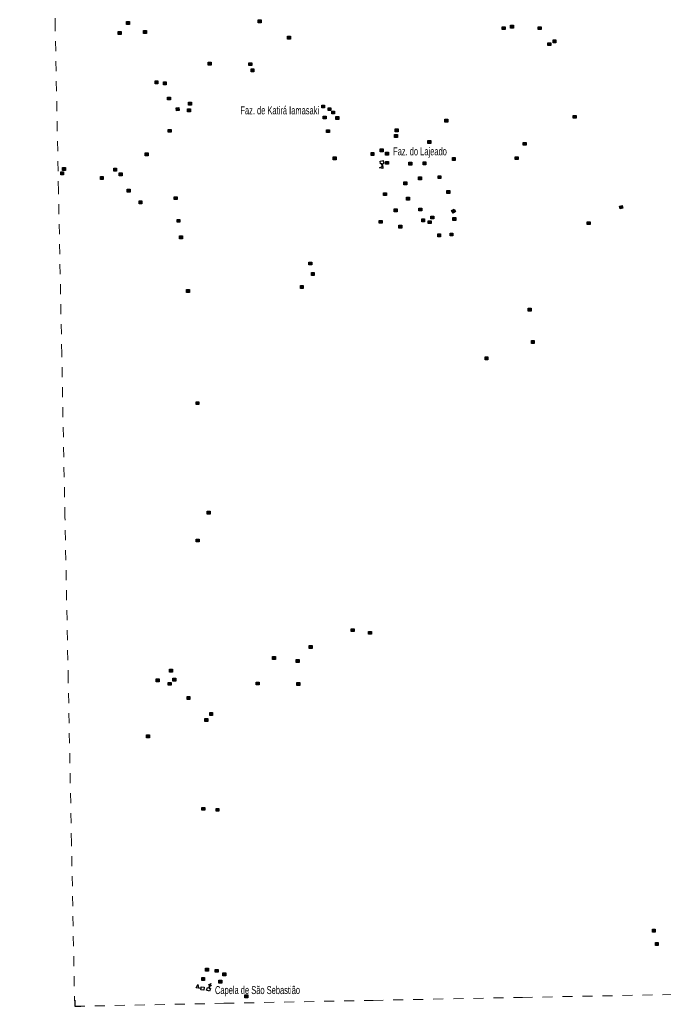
# Model space of a CAD drawing. Extents: x 220.8 to 246.7, y 7287.6 to 7315.8.
# Drawn here: x 220.75 to 227.18, y 7287.6 to 7297.47 of the extents above; entities that cross this region are included whole.
import ezdxf
from ezdxf.enums import TextEntityAlignment as Align

# ---------------------------------------------------------------- set-up
doc = ezdxf.new("R2010")
doc.units = 0
doc.header["$LTSCALE"] = 0.032
doc.linetypes.add('SHORT_DASHED', pattern=[2.7, 1.5, -1.2])
for name, color, linetype, lineweight in [('2', 7, 'Continuous', 25), ('4', 7, 'Continuous', 25), ('58', 7, 'SHORT_DASHED', 13), ('6', 7, 'Continuous', 25), ('63', 7, 'Continuous', 25)]:
    doc.layers.add(name, color=color, linetype=linetype, lineweight=lineweight)
doc.layers.add('61', color=7, linetype='Continuous')

msp = doc.modelspace()

# ---------------------------------------------------------------- hatches: boundary and pattern name
at = {"layer": '2'}
for points in [[(221.821, 7297.4477), (221.85, 7297.4477), (221.85, 7297.4187), (221.821, 7297.4187)], [(223.1357, 7297.4648), (223.1647, 7297.4648), (223.1647, 7297.4358), (223.1357, 7297.4358)], [(221.7374, 7297.348), (221.7664, 7297.348), (221.7664, 7297.319), (221.7374, 7297.319)], [(221.9914, 7297.3577), (222.0204, 7297.3577), (222.0204, 7297.3287), (221.9914, 7297.3287)], [(225.5724, 7297.3963), (225.6014, 7297.3963), (225.6014, 7297.3673), (225.5724, 7297.3673)], [(225.6572, 7297.412), (225.6862, 7297.412), (225.6862, 7297.383), (225.6572, 7297.383)], [(225.9335, 7297.3963), (225.9625, 7297.3963), (225.9625, 7297.3673), (225.9335, 7297.3673)], [(223.4296, 7297.3019), (223.4586, 7297.3019), (223.4586, 7297.2729), (223.4296, 7297.2729)], [(226.0308, 7297.2362), (226.0598, 7297.2362), (226.0598, 7297.2072), (226.0308, 7297.2072)], [(226.081, 7297.2644), (226.11, 7297.2644), (226.11, 7297.2354), (226.081, 7297.2354)], [(222.6359, 7297.0421), (222.6649, 7297.0421), (222.6649, 7297.0131), (222.6359, 7297.0131)], [(223.043, 7297.0363), (223.072, 7297.0363), (223.072, 7297.0073), (223.043, 7297.0073)], [(223.0644, 7296.9759), (223.0934, 7296.9759), (223.0934, 7296.9469), (223.0644, 7296.9469)], [(222.1059, 7296.854), (222.1349, 7296.854), (222.1349, 7296.825), (222.1059, 7296.825)], [(222.1888, 7296.845), (222.2178, 7296.845), (222.2178, 7296.816), (222.1888, 7296.816)], [(222.2303, 7296.6935), (222.2593, 7296.6935), (222.2593, 7296.6645), (222.2303, 7296.6645)], [(222.4412, 7296.6413), (222.4702, 7296.6413), (222.4702, 7296.6123), (222.4412, 7296.6123)], [(222.3155, 7296.5856), (222.3443, 7296.5889), (222.3477, 7296.5601), (222.3188, 7296.5567)], [(222.4304, 7296.5746), (222.4594, 7296.5746), (222.4594, 7296.5456), (222.4304, 7296.5456)], [(223.771, 7296.6131), (223.8, 7296.6131), (223.8, 7296.5841), (223.771, 7296.5841)], [(223.8339, 7296.5869), (223.8629, 7296.5869), (223.8629, 7296.5579), (223.8339, 7296.5579)], [(223.8706, 7296.5528), (223.8996, 7296.5528), (223.8996, 7296.5238), (223.8706, 7296.5238)], [(223.7867, 7296.5031), (223.8157, 7296.5031), (223.8157, 7296.4741), (223.7867, 7296.4741)], [(223.9125, 7296.4978), (223.9415, 7296.4978), (223.9415, 7296.4688), (223.9125, 7296.4688)], [(225.0007, 7296.4709), (225.0297, 7296.4709), (225.0297, 7296.4419), (225.0007, 7296.4419)], [(226.2829, 7296.5099), (226.3119, 7296.5099), (226.3119, 7296.4809), (226.2829, 7296.4809)], [(222.2371, 7296.3698), (222.2661, 7296.3698), (222.2661, 7296.3408), (222.2371, 7296.3408)], [(223.8182, 7296.3668), (223.8472, 7296.3668), (223.8472, 7296.3378), (223.8182, 7296.3378)], [(224.5043, 7296.3746), (224.5333, 7296.3746), (224.5333, 7296.3456), (224.5043, 7296.3456)], [(224.4984, 7296.318), (224.5274, 7296.318), (224.5274, 7296.289), (224.4984, 7296.289)], [(224.8313, 7296.259), (224.8603, 7296.259), (224.8603, 7296.23), (224.8313, 7296.23)], [(224.3555, 7296.1751), (224.3845, 7296.1751), (224.3845, 7296.1461), (224.3555, 7296.1461)], [(224.4091, 7296.1424), (224.4381, 7296.1424), (224.4381, 7296.1134), (224.4091, 7296.1134)], [(225.7831, 7296.2396), (225.8121, 7296.2396), (225.8121, 7296.2106), (225.7831, 7296.2106)], [(222.0066, 7296.1357), (222.0356, 7296.1357), (222.0356, 7296.1067), (222.0066, 7296.1067)], [(223.8851, 7296.0947), (223.9141, 7296.0947), (223.9141, 7296.0657), (223.8851, 7296.0657)], [(224.2632, 7296.1394), (224.2922, 7296.1394), (224.2922, 7296.1104), (224.2632, 7296.1104)], [(224.4091, 7296.0501), (224.4381, 7296.0501), (224.4381, 7296.0211), (224.4091, 7296.0211)], [(224.7827, 7296.0441), (224.8117, 7296.0441), (224.8117, 7296.0151), (224.7827, 7296.0151)], [(225.0756, 7296.0884), (225.1046, 7296.0884), (225.1046, 7296.0594), (225.0756, 7296.0594)], [(225.7036, 7296.0964), (225.7326, 7296.0964), (225.7326, 7296.0674), (225.7036, 7296.0674)], [(221.1639, 7295.9448), (221.1929, 7295.9448), (221.1929, 7295.9158), (221.1639, 7295.9158)], [(221.1819, 7295.988), (221.2109, 7295.988), (221.2109, 7295.959), (221.1819, 7295.959)], [(221.6933, 7295.9808), (221.7223, 7295.9808), (221.7223, 7295.9518), (221.6933, 7295.9518)], [(224.6413, 7296.0411), (224.6703, 7296.0411), (224.6703, 7296.0121), (224.6413, 7296.0121)], [(221.5601, 7295.898), (221.5891, 7295.898), (221.5891, 7295.869), (221.5601, 7295.869)], [(221.7473, 7295.934), (221.7763, 7295.934), (221.7763, 7295.905), (221.7473, 7295.905)], [(224.7384, 7295.8943), (224.7674, 7295.8943), (224.7674, 7295.8653), (224.7384, 7295.8653)], [(224.9323, 7295.9066), (224.9613, 7295.9066), (224.9613, 7295.8776), (224.9323, 7295.8776)], [(221.8288, 7295.7718), (221.8578, 7295.7718), (221.8578, 7295.7428), (221.8288, 7295.7428)], [(224.5906, 7295.8451), (224.6196, 7295.8451), (224.6196, 7295.8161), (224.5906, 7295.8161)], [(225.0216, 7295.7589), (225.0506, 7295.7589), (225.0506, 7295.7299), (225.0216, 7295.7299)], [(221.9459, 7295.6547), (221.9749, 7295.6547), (221.9749, 7295.6257), (221.9459, 7295.6257)], [(222.2973, 7295.6965), (222.3263, 7295.6965), (222.3263, 7295.6675), (222.2973, 7295.6675)], [(224.3875, 7295.7373), (224.4165, 7295.7373), (224.4165, 7295.7083), (224.3875, 7295.7083)], [(224.6184, 7295.6911), (224.6474, 7295.6911), (224.6474, 7295.6621), (224.6184, 7295.6621)], [(224.4952, 7295.5742), (224.5242, 7295.5742), (224.5242, 7295.5452), (224.4952, 7295.5452)], [(224.7415, 7295.5834), (224.7705, 7295.5834), (224.7705, 7295.5544), (224.7415, 7295.5544)], [(225.0685, 7295.5575), (225.0931, 7295.5728), (225.1085, 7295.5482), (225.0839, 7295.5329)], [(226.7446, 7295.6033), (226.7727, 7295.6106), (226.78, 7295.5825), (226.752, 7295.5752)], [(222.3252, 7295.4706), (222.3542, 7295.4706), (222.3542, 7295.4416), (222.3252, 7295.4416)], [(224.3444, 7295.4603), (224.3734, 7295.4603), (224.3734, 7295.4313), (224.3444, 7295.4313)], [(224.7692, 7295.4757), (224.7982, 7295.4757), (224.7982, 7295.4467), (224.7692, 7295.4467)], [(224.8338, 7295.4572), (224.8628, 7295.4572), (224.8628, 7295.4282), (224.8338, 7295.4282)], [(224.8615, 7295.5034), (224.8905, 7295.5034), (224.8905, 7295.4744), (224.8615, 7295.4744)], [(225.0801, 7295.488), (225.1091, 7295.488), (225.1091, 7295.459), (225.0801, 7295.459)], [(224.5414, 7295.411), (224.5704, 7295.411), (224.5704, 7295.382), (224.5414, 7295.382)], [(226.4225, 7295.4471), (226.4515, 7295.4471), (226.4515, 7295.4181), (226.4225, 7295.4181)], [(222.3503, 7295.306), (222.3793, 7295.306), (222.3793, 7295.277), (222.3503, 7295.277)], [(224.9293, 7295.3248), (224.9583, 7295.3248), (224.9583, 7295.2958), (224.9293, 7295.2958)], [(225.0524, 7295.3341), (225.0814, 7295.3341), (225.0814, 7295.3051), (225.0524, 7295.3051)], [(223.6429, 7295.0432), (223.6719, 7295.0432), (223.6719, 7295.0142), (223.6429, 7295.0142)], [(223.6678, 7294.9381), (223.6968, 7294.9381), (223.6968, 7294.9091), (223.6678, 7294.9091)], [(222.4202, 7294.7687), (222.4492, 7294.7687), (222.4492, 7294.7397), (222.4202, 7294.7397)], [(223.5574, 7294.8085), (223.5864, 7294.8085), (223.5864, 7294.7795), (223.5574, 7294.7795)], [(225.8327, 7294.581), (225.8617, 7294.581), (225.8617, 7294.552), (225.8327, 7294.552)], [(225.865, 7294.2581), (225.894, 7294.2581), (225.894, 7294.2291), (225.865, 7294.2291)], [(225.4022, 7294.0967), (225.4312, 7294.0967), (225.4312, 7294.0677), (225.4022, 7294.0677)], [(222.5156, 7293.6474), (222.5446, 7293.6474), (222.5446, 7293.6184), (222.5156, 7293.6184)], [(222.6278, 7292.5537), (222.6568, 7292.5537), (222.6568, 7292.5247), (222.6278, 7292.5247)], [(222.5162, 7292.2747), (222.5452, 7292.2747), (222.5452, 7292.2457), (222.5162, 7292.2457)], [(224.0653, 7291.378), (224.0943, 7291.378), (224.0943, 7291.349), (224.0653, 7291.349)], [(224.2372, 7291.3515), (224.2662, 7291.3515), (224.2662, 7291.3225), (224.2372, 7291.3225)], [(223.6455, 7291.2094), (223.6745, 7291.2094), (223.6745, 7291.1804), (223.6455, 7291.1804)], [(223.2785, 7291.1003), (223.3075, 7291.1003), (223.3075, 7291.0713), (223.2785, 7291.0713)], [(223.5165, 7291.0705), (223.5455, 7291.0705), (223.5455, 7291.0415), (223.5165, 7291.0415)], [(222.25, 7290.9735), (222.279, 7290.9735), (222.279, 7290.9445), (222.25, 7290.9445)], [(222.1182, 7290.8755), (222.1472, 7290.8755), (222.1472, 7290.8465), (222.1182, 7290.8465)], [(222.2365, 7290.8417), (222.2655, 7290.8417), (222.2655, 7290.8127), (222.2365, 7290.8127)], [(222.2838, 7290.8823), (222.3128, 7290.8823), (222.3128, 7290.8533), (222.2838, 7290.8533)], [(223.1166, 7290.8451), (223.1456, 7290.8451), (223.1456, 7290.8161), (223.1166, 7290.8161)], [(223.5231, 7290.8391), (223.5521, 7290.8391), (223.5521, 7290.8101), (223.5231, 7290.8101)], [(222.4257, 7290.6998), (222.4547, 7290.6998), (222.4547, 7290.6708), (222.4257, 7290.6708)], [(222.652, 7290.541), (222.681, 7290.541), (222.681, 7290.512), (222.652, 7290.512)], [(222.6047, 7290.4802), (222.6337, 7290.4802), (222.6337, 7290.4512), (222.6047, 7290.4512)], [(222.0207, 7290.3172), (222.0497, 7290.3172), (222.0497, 7290.2882), (222.0207, 7290.2882)], [(222.5736, 7289.5915), (222.6026, 7289.5915), (222.6026, 7289.5625), (222.5736, 7289.5625)], [(222.715, 7289.5816), (222.744, 7289.5816), (222.744, 7289.5526), (222.715, 7289.5526)], [(227.0736, 7288.3731), (227.1026, 7288.3731), (227.1026, 7288.3441), (227.0736, 7288.3441)], [(227.1033, 7288.2411), (227.1323, 7288.2411), (227.1323, 7288.2121), (227.1033, 7288.2121)], [(222.6094, 7287.9844), (222.6384, 7287.9844), (222.6384, 7287.9554), (222.6094, 7287.9554)], [(222.7071, 7287.9719), (222.7361, 7287.9719), (222.7361, 7287.9429), (222.7071, 7287.9429)], [(222.5719, 7287.8908), (222.6009, 7287.8908), (222.6009, 7287.8618), (222.5719, 7287.8618)], [(222.7424, 7287.8638), (222.7714, 7287.8638), (222.7714, 7287.8348), (222.7424, 7287.8348)], [(222.784, 7287.9366), (222.813, 7287.9366), (222.813, 7287.9076), (222.784, 7287.9076)], [(223.0022, 7287.7162), (223.0312, 7287.7162), (223.0312, 7287.6872), (223.0022, 7287.6872)]]:
    msp.add_hatch(color=256, dxfattribs=at).paths.add_polyline_path(points)

# ---------------------------------------------------------------- linework, layer by layer
for points in [[(221.821, 7297.4477), (221.85, 7297.4477), (221.85, 7297.4187), (221.821, 7297.4187)], [(223.1357, 7297.4648), (223.1647, 7297.4648), (223.1647, 7297.4358), (223.1357, 7297.4358)], [(221.7374, 7297.348), (221.7664, 7297.348), (221.7664, 7297.319), (221.7374, 7297.319)], [(221.9914, 7297.3577), (222.0204, 7297.3577), (222.0204, 7297.3287), (221.9914, 7297.3287)], [(225.5724, 7297.3963), (225.6014, 7297.3963), (225.6014, 7297.3673), (225.5724, 7297.3673)], [(225.6572, 7297.412), (225.6862, 7297.412), (225.6862, 7297.383), (225.6572, 7297.383)], [(225.9335, 7297.3963), (225.9625, 7297.3963), (225.9625, 7297.3673), (225.9335, 7297.3673)], [(223.4296, 7297.3019), (223.4586, 7297.3019), (223.4586, 7297.2729), (223.4296, 7297.2729)], [(226.0308, 7297.2362), (226.0598, 7297.2362), (226.0598, 7297.2072), (226.0308, 7297.2072)], [(226.081, 7297.2644), (226.11, 7297.2644), (226.11, 7297.2354), (226.081, 7297.2354)], [(222.6359, 7297.0421), (222.6649, 7297.0421), (222.6649, 7297.0131), (222.6359, 7297.0131)], [(223.043, 7297.0363), (223.072, 7297.0363), (223.072, 7297.0073), (223.043, 7297.0073)], [(223.0644, 7296.9759), (223.0934, 7296.9759), (223.0934, 7296.9469), (223.0644, 7296.9469)], [(222.1059, 7296.854), (222.1349, 7296.854), (222.1349, 7296.825), (222.1059, 7296.825)], [(222.1888, 7296.845), (222.2178, 7296.845), (222.2178, 7296.816), (222.1888, 7296.816)], [(222.2303, 7296.6935), (222.2593, 7296.6935), (222.2593, 7296.6645), (222.2303, 7296.6645)], [(222.4412, 7296.6413), (222.4702, 7296.6413), (222.4702, 7296.6123), (222.4412, 7296.6123)], [(222.3155, 7296.5856), (222.3443, 7296.5889), (222.3477, 7296.5601), (222.3188, 7296.5567)], [(222.4304, 7296.5746), (222.4594, 7296.5746), (222.4594, 7296.5456), (222.4304, 7296.5456)], [(223.771, 7296.6131), (223.8, 7296.6131), (223.8, 7296.5841), (223.771, 7296.5841)], [(223.8339, 7296.5869), (223.8629, 7296.5869), (223.8629, 7296.5579), (223.8339, 7296.5579)], [(223.8706, 7296.5528), (223.8996, 7296.5528), (223.8996, 7296.5238), (223.8706, 7296.5238)], [(223.7867, 7296.5031), (223.8157, 7296.5031), (223.8157, 7296.4741), (223.7867, 7296.4741)], [(223.9125, 7296.4978), (223.9415, 7296.4978), (223.9415, 7296.4688), (223.9125, 7296.4688)], [(225.0007, 7296.4709), (225.0297, 7296.4709), (225.0297, 7296.4419), (225.0007, 7296.4419)], [(226.2829, 7296.5099), (226.3119, 7296.5099), (226.3119, 7296.4809), (226.2829, 7296.4809)], [(222.2371, 7296.3698), (222.2661, 7296.3698), (222.2661, 7296.3408), (222.2371, 7296.3408)], [(223.8182, 7296.3668), (223.8472, 7296.3668), (223.8472, 7296.3378), (223.8182, 7296.3378)], [(224.5043, 7296.3746), (224.5333, 7296.3746), (224.5333, 7296.3456), (224.5043, 7296.3456)], [(224.4984, 7296.318), (224.5274, 7296.318), (224.5274, 7296.289), (224.4984, 7296.289)], [(224.8313, 7296.259), (224.8603, 7296.259), (224.8603, 7296.23), (224.8313, 7296.23)], [(224.3555, 7296.1751), (224.3845, 7296.1751), (224.3845, 7296.1461), (224.3555, 7296.1461)], [(224.4091, 7296.1424), (224.4381, 7296.1424), (224.4381, 7296.1134), (224.4091, 7296.1134)], [(225.7831, 7296.2396), (225.8121, 7296.2396), (225.8121, 7296.2106), (225.7831, 7296.2106)], [(222.0066, 7296.1357), (222.0356, 7296.1357), (222.0356, 7296.1067), (222.0066, 7296.1067)], [(223.8851, 7296.0947), (223.9141, 7296.0947), (223.9141, 7296.0657), (223.8851, 7296.0657)], [(224.2632, 7296.1394), (224.2922, 7296.1394), (224.2922, 7296.1104), (224.2632, 7296.1104)], [(224.4091, 7296.0501), (224.4381, 7296.0501), (224.4381, 7296.0211), (224.4091, 7296.0211)], [(224.7827, 7296.0441), (224.8117, 7296.0441), (224.8117, 7296.0151), (224.7827, 7296.0151)], [(225.0756, 7296.0884), (225.1046, 7296.0884), (225.1046, 7296.0594), (225.0756, 7296.0594)], [(225.7036, 7296.0964), (225.7326, 7296.0964), (225.7326, 7296.0674), (225.7036, 7296.0674)], [(221.1639, 7295.9448), (221.1929, 7295.9448), (221.1929, 7295.9158), (221.1639, 7295.9158)], [(221.1819, 7295.988), (221.2109, 7295.988), (221.2109, 7295.959), (221.1819, 7295.959)], [(221.6933, 7295.9808), (221.7223, 7295.9808), (221.7223, 7295.9518), (221.6933, 7295.9518)], [(224.6413, 7296.0411), (224.6703, 7296.0411), (224.6703, 7296.0121), (224.6413, 7296.0121)], [(221.5601, 7295.898), (221.5891, 7295.898), (221.5891, 7295.869), (221.5601, 7295.869)], [(221.7473, 7295.934), (221.7763, 7295.934), (221.7763, 7295.905), (221.7473, 7295.905)], [(224.7384, 7295.8943), (224.7674, 7295.8943), (224.7674, 7295.8653), (224.7384, 7295.8653)], [(224.9323, 7295.9066), (224.9613, 7295.9066), (224.9613, 7295.8776), (224.9323, 7295.8776)], [(221.8288, 7295.7718), (221.8578, 7295.7718), (221.8578, 7295.7428), (221.8288, 7295.7428)], [(224.5906, 7295.8451), (224.6196, 7295.8451), (224.6196, 7295.8161), (224.5906, 7295.8161)], [(225.0216, 7295.7589), (225.0506, 7295.7589), (225.0506, 7295.7299), (225.0216, 7295.7299)], [(221.9459, 7295.6547), (221.9749, 7295.6547), (221.9749, 7295.6257), (221.9459, 7295.6257)], [(222.2973, 7295.6965), (222.3263, 7295.6965), (222.3263, 7295.6675), (222.2973, 7295.6675)], [(224.3875, 7295.7373), (224.4165, 7295.7373), (224.4165, 7295.7083), (224.3875, 7295.7083)], [(224.6184, 7295.6911), (224.6474, 7295.6911), (224.6474, 7295.6621), (224.6184, 7295.6621)], [(224.4952, 7295.5742), (224.5242, 7295.5742), (224.5242, 7295.5452), (224.4952, 7295.5452)], [(224.7415, 7295.5834), (224.7705, 7295.5834), (224.7705, 7295.5544), (224.7415, 7295.5544)], [(225.0685, 7295.5575), (225.0931, 7295.5728), (225.1085, 7295.5482), (225.0839, 7295.5329)], [(226.7446, 7295.6033), (226.7727, 7295.6106), (226.78, 7295.5825), (226.752, 7295.5752)], [(222.3252, 7295.4706), (222.3542, 7295.4706), (222.3542, 7295.4416), (222.3252, 7295.4416)], [(224.3444, 7295.4603), (224.3734, 7295.4603), (224.3734, 7295.4313), (224.3444, 7295.4313)], [(224.7692, 7295.4757), (224.7982, 7295.4757), (224.7982, 7295.4467), (224.7692, 7295.4467)], [(224.8338, 7295.4572), (224.8628, 7295.4572), (224.8628, 7295.4282), (224.8338, 7295.4282)], [(224.8615, 7295.5034), (224.8905, 7295.5034), (224.8905, 7295.4744), (224.8615, 7295.4744)], [(225.0801, 7295.488), (225.1091, 7295.488), (225.1091, 7295.459), (225.0801, 7295.459)], [(224.5414, 7295.411), (224.5704, 7295.411), (224.5704, 7295.382), (224.5414, 7295.382)], [(226.4225, 7295.4471), (226.4515, 7295.4471), (226.4515, 7295.4181), (226.4225, 7295.4181)], [(222.3503, 7295.306), (222.3793, 7295.306), (222.3793, 7295.277), (222.3503, 7295.277)], [(224.9293, 7295.3248), (224.9583, 7295.3248), (224.9583, 7295.2958), (224.9293, 7295.2958)], [(225.0524, 7295.3341), (225.0814, 7295.3341), (225.0814, 7295.3051), (225.0524, 7295.3051)], [(223.6429, 7295.0432), (223.6719, 7295.0432), (223.6719, 7295.0142), (223.6429, 7295.0142)], [(223.6678, 7294.9381), (223.6968, 7294.9381), (223.6968, 7294.9091), (223.6678, 7294.9091)], [(222.4202, 7294.7687), (222.4492, 7294.7687), (222.4492, 7294.7397), (222.4202, 7294.7397)], [(223.5574, 7294.8085), (223.5864, 7294.8085), (223.5864, 7294.7795), (223.5574, 7294.7795)], [(225.8327, 7294.581), (225.8617, 7294.581), (225.8617, 7294.552), (225.8327, 7294.552)], [(225.865, 7294.2581), (225.894, 7294.2581), (225.894, 7294.2291), (225.865, 7294.2291)], [(225.4022, 7294.0967), (225.4312, 7294.0967), (225.4312, 7294.0677), (225.4022, 7294.0677)], [(222.5156, 7293.6474), (222.5446, 7293.6474), (222.5446, 7293.6184), (222.5156, 7293.6184)], [(222.6278, 7292.5537), (222.6568, 7292.5537), (222.6568, 7292.5247), (222.6278, 7292.5247)], [(222.5162, 7292.2747), (222.5452, 7292.2747), (222.5452, 7292.2457), (222.5162, 7292.2457)], [(224.0653, 7291.378), (224.0943, 7291.378), (224.0943, 7291.349), (224.0653, 7291.349)], [(224.2372, 7291.3515), (224.2662, 7291.3515), (224.2662, 7291.3225), (224.2372, 7291.3225)], [(223.6455, 7291.2094), (223.6745, 7291.2094), (223.6745, 7291.1804), (223.6455, 7291.1804)], [(223.2785, 7291.1003), (223.3075, 7291.1003), (223.3075, 7291.0713), (223.2785, 7291.0713)], [(223.5165, 7291.0705), (223.5455, 7291.0705), (223.5455, 7291.0415), (223.5165, 7291.0415)], [(222.25, 7290.9735), (222.279, 7290.9735), (222.279, 7290.9445), (222.25, 7290.9445)], [(222.1182, 7290.8755), (222.1472, 7290.8755), (222.1472, 7290.8465), (222.1182, 7290.8465)], [(222.2365, 7290.8417), (222.2655, 7290.8417), (222.2655, 7290.8127), (222.2365, 7290.8127)], [(222.2838, 7290.8823), (222.3128, 7290.8823), (222.3128, 7290.8533), (222.2838, 7290.8533)], [(223.1166, 7290.8451), (223.1456, 7290.8451), (223.1456, 7290.8161), (223.1166, 7290.8161)], [(223.5231, 7290.8391), (223.5521, 7290.8391), (223.5521, 7290.8101), (223.5231, 7290.8101)], [(222.4257, 7290.6998), (222.4547, 7290.6998), (222.4547, 7290.6708), (222.4257, 7290.6708)], [(222.652, 7290.541), (222.681, 7290.541), (222.681, 7290.512), (222.652, 7290.512)], [(222.6047, 7290.4802), (222.6337, 7290.4802), (222.6337, 7290.4512), (222.6047, 7290.4512)], [(222.0207, 7290.3172), (222.0497, 7290.3172), (222.0497, 7290.2882), (222.0207, 7290.2882)], [(222.5736, 7289.5915), (222.6026, 7289.5915), (222.6026, 7289.5625), (222.5736, 7289.5625)], [(222.715, 7289.5816), (222.744, 7289.5816), (222.744, 7289.5526), (222.715, 7289.5526)], [(227.0736, 7288.3731), (227.1026, 7288.3731), (227.1026, 7288.3441), (227.0736, 7288.3441)], [(227.1033, 7288.2411), (227.1323, 7288.2411), (227.1323, 7288.2121), (227.1033, 7288.2121)], [(222.6094, 7287.9844), (222.6384, 7287.9844), (222.6384, 7287.9554), (222.6094, 7287.9554)], [(222.7071, 7287.9719), (222.7361, 7287.9719), (222.7361, 7287.9429), (222.7071, 7287.9429)], [(222.5719, 7287.8908), (222.6009, 7287.8908), (222.6009, 7287.8618), (222.5719, 7287.8618)], [(222.7424, 7287.8638), (222.7714, 7287.8638), (222.7714, 7287.8348), (222.7424, 7287.8348)], [(222.784, 7287.9366), (222.813, 7287.9366), (222.813, 7287.9076), (222.784, 7287.9076)], [(223.0022, 7287.7162), (223.0312, 7287.7162), (223.0312, 7287.6872), (223.0022, 7287.6872)]]:
    msp.add_lwpolyline(points, close=True, dxfattribs=at)
at = {"layer": '4'}
for points in [[(224.3713, 7296.0264), (224.3593, 7296.025), (224.3557, 7296.0537), (224.3845, 7296.0573), (224.3881, 7296.0285), (224.3762, 7296.027)], [(224.3762, 7296.027), (224.3821, 7295.979), (224.347, 7295.9864), (224.3745, 7296.0005), (224.3713, 7296.0264)], [(222.5655, 7287.7805), (222.5177, 7287.7877), (222.5342, 7287.8195), (222.5404, 7287.7892), (222.5663, 7287.7854)], [(222.5663, 7287.7854), (222.568, 7287.7973), (222.5967, 7287.7931), (222.5924, 7287.7644), (222.5638, 7287.7687), (222.5655, 7287.7805)]]:
    msp.add_lwpolyline(points, dxfattribs=at)
at = {"layer": '58'}
for points in [[(221.3035, 7287.6034), (221.271, 7289.2329), (221.2386, 7290.8624), (221.2062, 7292.4919), (221.1738, 7294.1214), (221.1414, 7295.7509), (221.109, 7297.3804), (221.0767, 7299.0099), (221.0443, 7300.6394), (221.0121, 7302.2689), (220.9798, 7303.8984), (220.9475, 7305.5279), (220.9153, 7307.1574), (220.883, 7308.7869), (220.8508, 7310.4164), (220.8187, 7312.0459), (220.7865, 7313.6754), (220.7543, 7315.3049)], [(221.3035, 7287.6034), (222.7945, 7287.633), (224.2855, 7287.6625), (225.7765, 7287.6918), (227.2675, 7287.7209), (228.7585, 7287.7499), (230.2495, 7287.7787), (231.7405, 7287.8074), (233.2315, 7287.836), (234.7225, 7287.8643), (236.2135, 7287.8925), (237.7045, 7287.9205), (239.1956, 7287.9483), (240.6866, 7287.9761), (242.1776, 7288.0036), (243.6686, 7288.031), (245.1597, 7288.0583), (246.6507, 7288.0853)]]:
    msp.add_lwpolyline(points, dxfattribs=at)
at = {"layer": '6'}
for points in [[(222.6469, 7287.785), (222.6583, 7287.7809), (222.6486, 7287.7536), (222.6212, 7287.7633), (222.6309, 7287.7906), (222.6423, 7287.7866)], [(222.6423, 7287.7866), (222.6514, 7287.8121), (222.64, 7287.8161), (222.6416, 7287.8208), (222.653, 7287.8167), (222.6585, 7287.8322), (222.6631, 7287.8306), (222.6576, 7287.8151), (222.669, 7287.8111), (222.6673, 7287.8064), (222.6559, 7287.8105), (222.6469, 7287.785)]]:
    msp.add_lwpolyline(points, dxfattribs=at)
at = {"layer": '63'}
msp.add_lwpolyline([(221.3035, 7287.665), (221.3035, 7287.6034), (221.3642, 7287.6034)], dxfattribs=at)

# ---------------------------------------------------------------- texts
at = {"layer": '61', "width": 0.7}
msp.add_text('Faz. de Katirá Iamasaki', height=0.08, dxfattribs=at).set_placement((223.7446, 7296.5203), align=Align.RIGHT)
for s, p in [('Faz. do Lajeado', (224.4836, 7296.1105)), ('Capela de São Sebastião', (222.7044, 7287.7254))]:
    msp.add_text(s, height=0.08, dxfattribs=at).set_placement(p)

doc.saveas('drawing.dxf')
